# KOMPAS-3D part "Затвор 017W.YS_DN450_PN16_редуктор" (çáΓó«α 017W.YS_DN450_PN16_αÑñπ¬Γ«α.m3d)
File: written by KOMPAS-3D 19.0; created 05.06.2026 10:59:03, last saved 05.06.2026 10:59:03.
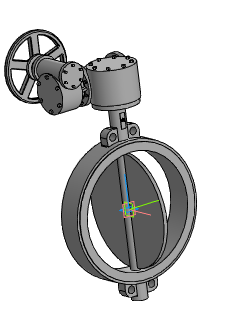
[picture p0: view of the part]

Document properties: Автор: Энергия; Полное имя файла: ..\..\..\3d для проектировщиков\x.x Тип 017W.Y(S) Затвор дисковый поворотный межфланцевый\Затвор 017W.Y(S)_DN50-DN1200_редуктор\Затвор 017W.YS_DN450_PN16_редуктор.a3d

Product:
- Part/product: Затвор 017W.YS_DN450_PN16_редуктор
    Масса: 152.645

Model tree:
1. Операция без истории:1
